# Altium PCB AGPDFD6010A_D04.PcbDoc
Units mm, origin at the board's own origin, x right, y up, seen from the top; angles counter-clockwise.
Board outline 100.4 x 100.27 mm, 2 copper layers (Top Layer, Bottom Layer), stack 1.57 mm thick; 22 components, 16 nets, 92 pads, 437 vias.
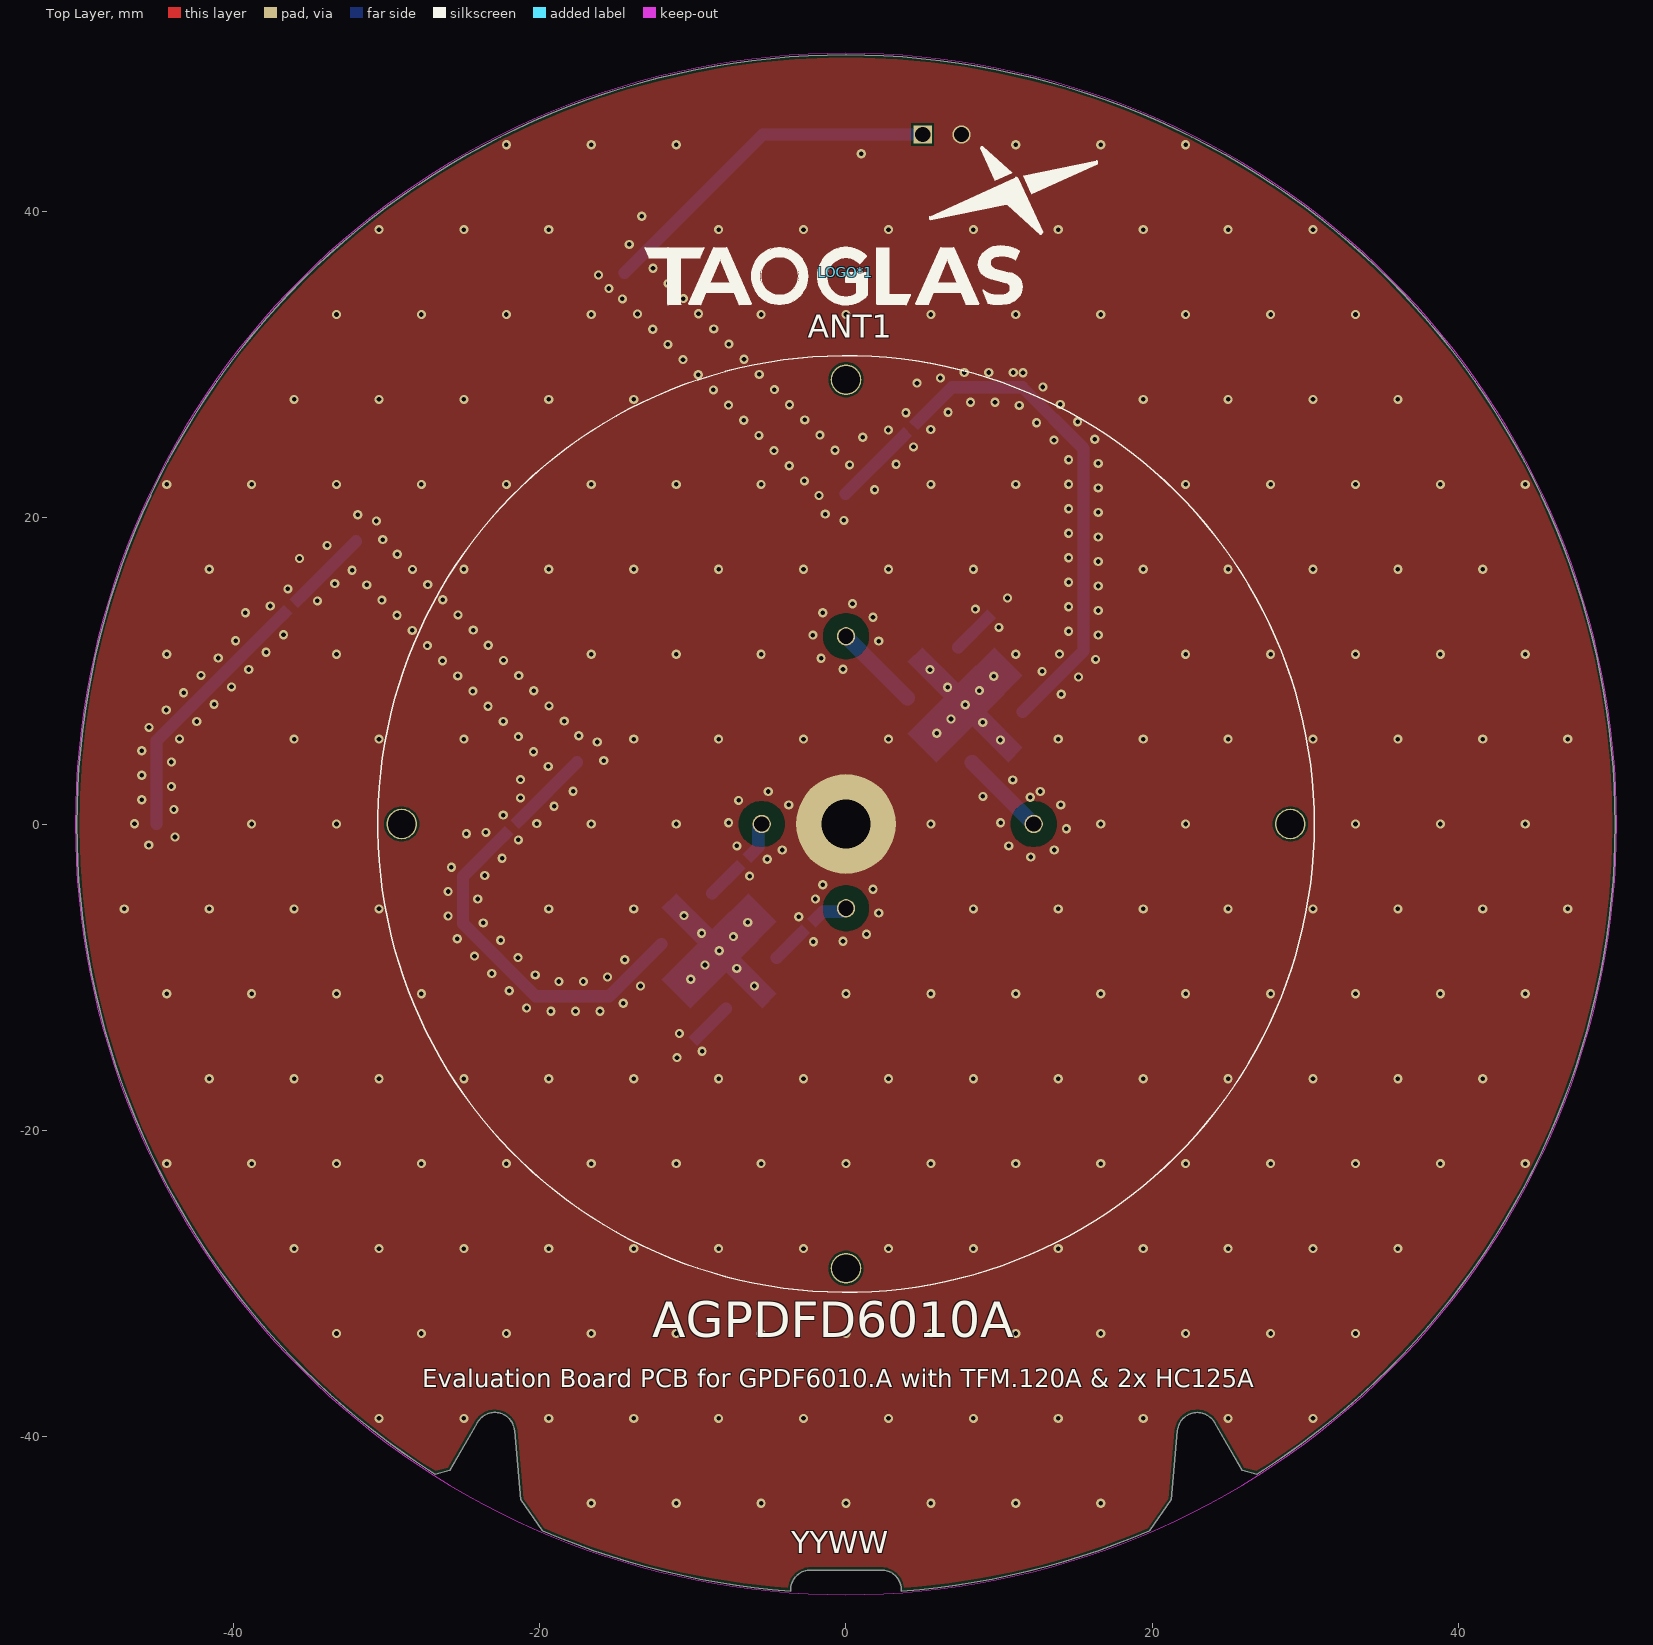
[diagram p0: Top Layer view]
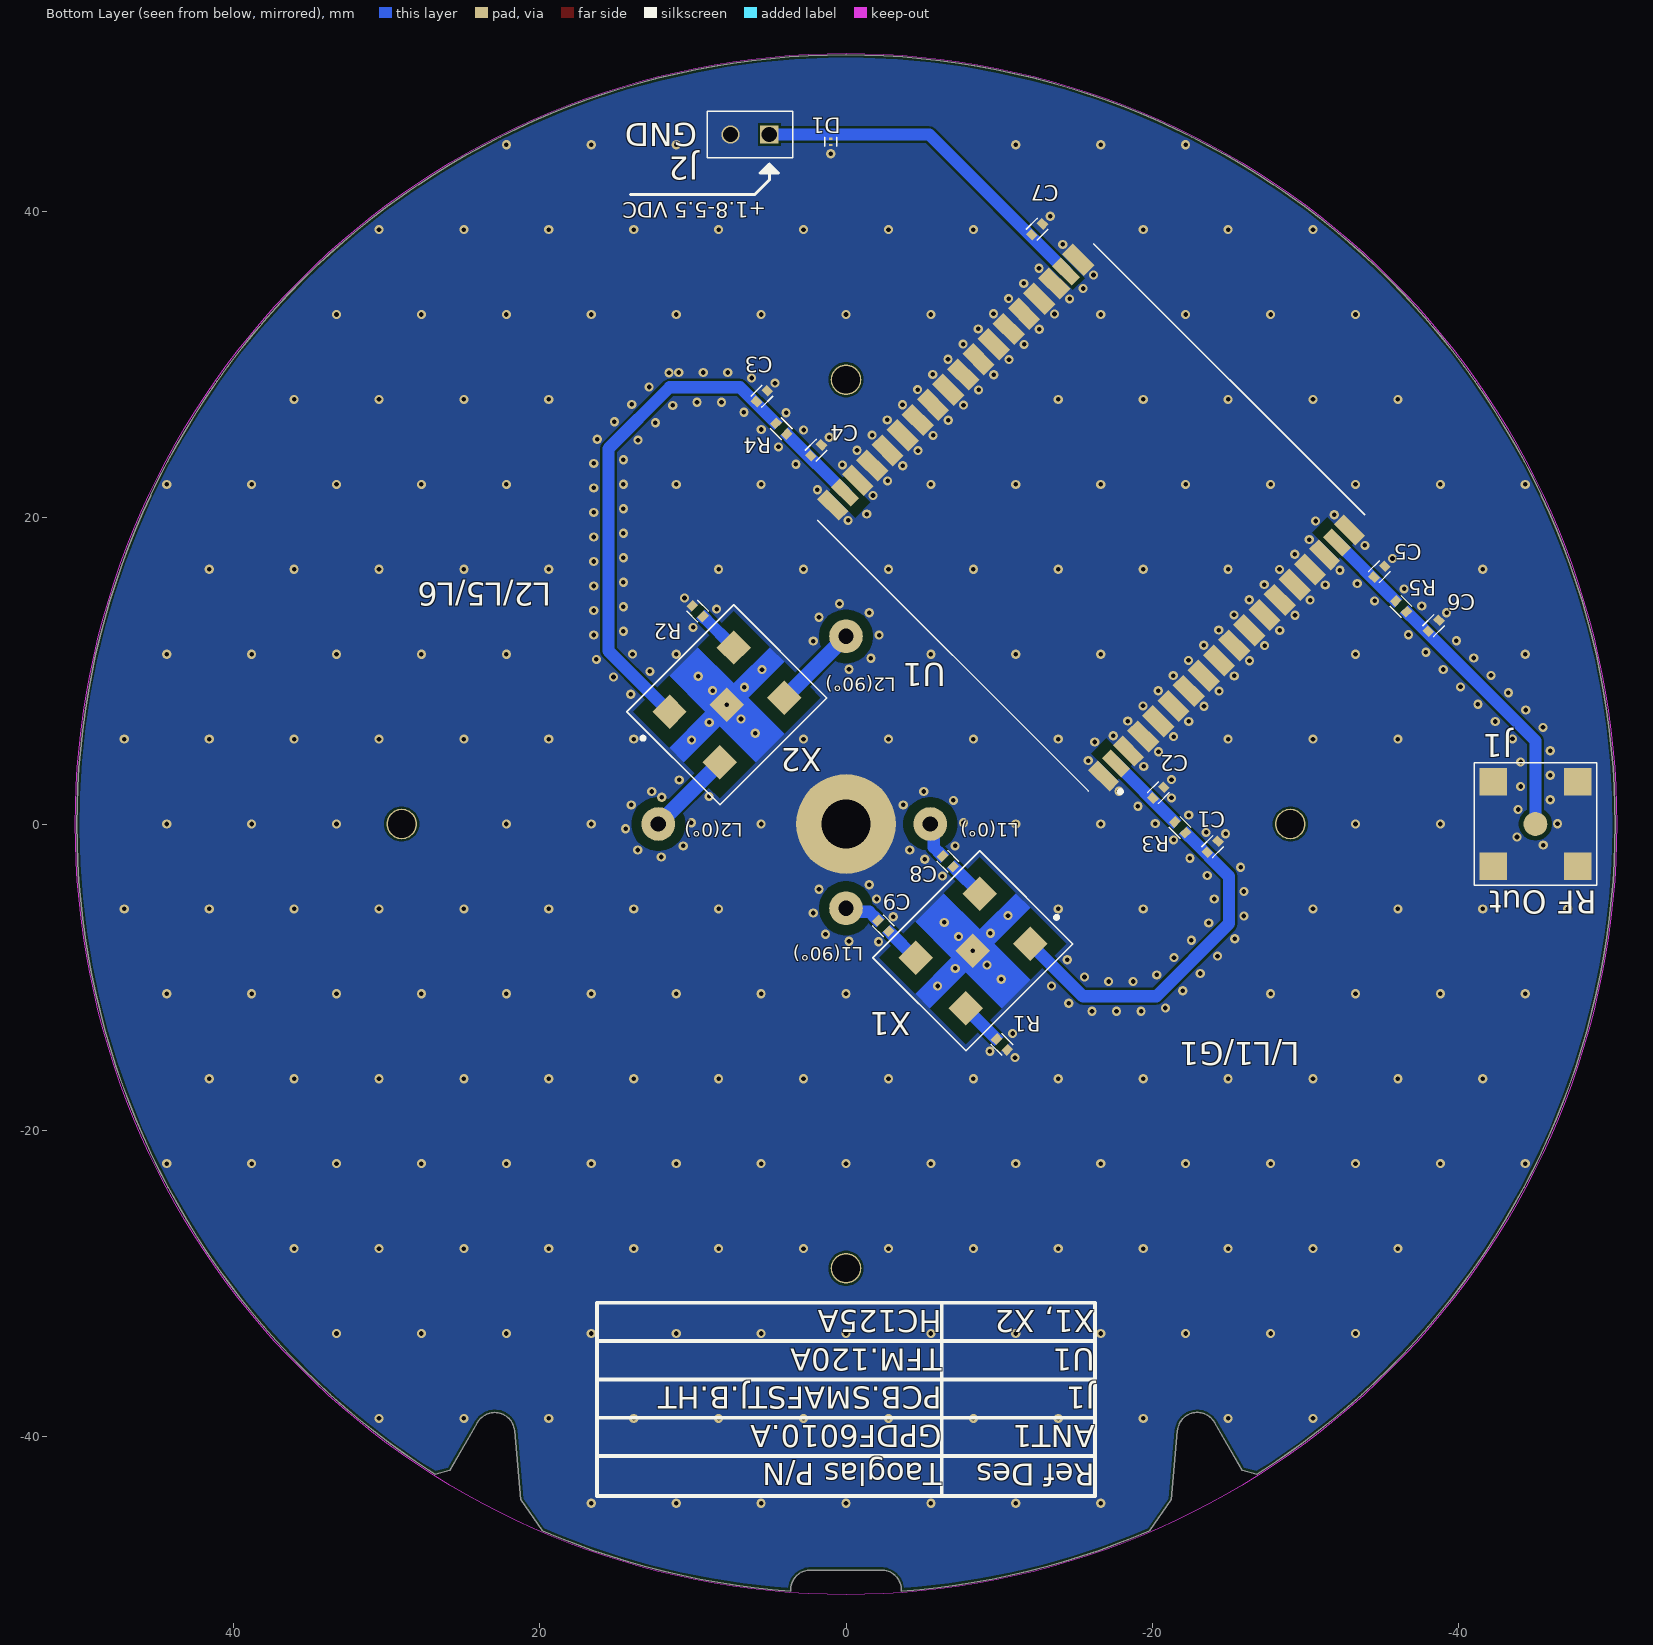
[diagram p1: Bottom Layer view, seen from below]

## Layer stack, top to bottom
Top Solder Mask: solder mask 0.01, Solder Resist, Dk 3.5
Top Layer: signal copper 0.035
Dielectric: core 1.5, FR-4, Dk 4.2
Bottom Layer: signal copper 0.035
Bottom Solder Mask: solder mask 0.01, Solder Resist, Dk 3.5

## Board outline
-19.822,-46.121 ccw(c0,0) -3.611,-50.07 -3.611,-49.992 cw(c-2.311,-49.992) -2.311,-48.692 2.311,-48.692 cw(c2.311,-49.992) 3.611,-49.992 3.611,-50.07 ccw(c0,0) 19.822,-46.121 21.236,-44.101 21.631,-39.593 cw(c22.926,-39.707) 24.052,-39.057 24.051,-39.057 25.857,-42.185 26.812,-42.44 ccw(c0,0) -26.812,-42.44 -25.857,-42.185 -24.051,-39.057 cw(c-22.926,-39.706) -21.632,-39.594 -21.63,-39.593 -21.236,-44.101

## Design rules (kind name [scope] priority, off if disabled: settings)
BoardOutlineClearance [All] p1: gap=0.196 ignorepadtopadclearanceinfootprint=FALSE
Clearance Clearance_Polygon [All] p1: gap=0.14 ignorepadtopadclearanceinfootprint=FALSE except(0.05: Arc-Arc Arc-Track Track-Track; 0.1: Arc-SMDPad Arc-THPad Track-SMDPad Track-THPad SMDPad-SMDPad SMDPad-THPad THPad-THPad; 0.2: Arc-Via Arc-Text Arc-Hole Track-Via Track-Text Track-Hole SMDPad-Via SMDPad-Text SMDPad-Hole THPad-Via THPad-Text THPad-Hole Via-Via Via-Text Via-Hole Fill-Text Fill-Hole Poly-Text Poly-Hole Region-Text Region-Hole Text-Text Text-Hole)
HoleSize [All] p1: absolutevalues=TRUE maxlimit=6 minlimit=0.15 maxpercent=80.000 minpercent=20.000
MinimumAnnularRing [All] p1: minimumring=0.1
MinimumSolderMaskSliver [All vs InPadClass('All Pads')] p1: minsoldermaskwidth=0.05
PolygonConnect [All] p1: connectstyle=Direct reliefconductorwidth=0.254 reliefentries=4 polygonreliefangle="90 Angle" airgapwidth=0.254
RoutingVias [All] p1: holewidth=0.3 width=0.8 viastyle="Through Hole" minholewidth=0.15 minwidth=0.65 maxholewidth=6 maxwidth=6.5
SilkToSilkClearance [All] p1: silktosilkclearance=0.1
SilkToSolderMaskClearance [IsPad or IsVia vs OnLayer('Top Overlay')] p1: minsilkscreentomaskgap=0.05 clearancetoexposedcopper=FALSE
SilkToSolderMaskClearance SilkToSolderMaskClearance_1 [IsPad or IsVia vs OnLayer('Bottom Overlay')] p2: minsilkscreentomaskgap=0.05 clearancetoexposedcopper=FALSE
SolderMaskExpansion [Not IsVia] p1: expansion=0.1 istentingtop=FALSE
Width [All] p1: maxlimit=5 minlimit=0.1 preferedwidth=1 minimp=50.000000 maximp=50.000000 favimp=50.000000
26 further rules are at their usual default settings.

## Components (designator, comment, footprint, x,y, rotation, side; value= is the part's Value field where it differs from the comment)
ANT1 "TAOGLAS_GPDF6010.A" TAOGLAS_GPDF6010.A 0,0 r0 top
C1 "DNF" "0402 - DNF" -23.923,-1.488 r135 bottom
C2 "DNF" "0402 - DNF" -20.388,2.048 r135 bottom
C3 "DNF" "0402 - DNF" 5.488,27.924 r135 bottom
C4 "DNF" "0402 - DNF" 1.952,24.388 r135 bottom
C5 "DNF" "0402 - DNF" -34.812,16.472 r315 bottom
C6 "DNF" "0402 - DNF" -38.348,12.936 r135 bottom
C7 "100pF" "Capacitor - 0402 - GRM" -12.472,38.812 r315 bottom
C8 "4.7pF" "Capacitor - 0402 - GRM" -6.653,-2.442 r45 bottom
C9 "4.7pF" "Capacitor - 0402 - GRM" -2.442,-6.653 r45 bottom
D1 "ESD245B1W0201E6327XTSA1" "Diode - 0201 (0603 Metric) - DSN0603-2" 1,44.525 r270 bottom
J1 "TAOGLAS_PCB.SMAFSTJ.B.HT" TAOGLAS_PCB.SMAFSTJ.B.HT -45,0 r270 bottom
J2 "PREC002SAAN-RC" SULLINS_PREC002SAAN-RC 6.27,45 r0 bottom
LOGO*1 "TAOGLAS_LOGO" "TAOGLAS_LOGO - No R - 10.3mm" 0,36 r0 top
R1 "Resistor_Thick Film_1005(0402)_49.9Ohms+-1%_0.063W" "Resistor - 0402 - RC_L" -10.179,-14.391 r225 bottom value=49.9
R2 "Resistor_Thick Film_1005(0402)_49.9Ohms+-1%_0.063W" "Resistor - 0402 - RC_L" 9.686,13.898 r45 bottom value=49.9
R3 "Resistor_Thick Film_1005(0402)_0Ohm" "Resistor - 0402 - RC_L" -21.802,-0.22 r225 bottom value=0
R4 "Resistor_Thick Film_1005(0402)_0Ohm" "Resistor - 0402 - RC_L" 4.22,25.802 r45 bottom value=0
R5 "Resistor_Thick Film_1005(0402)_0Ohm" "Resistor - 0402 - RC_L" -36.226,14.204 r225 bottom value=0
U1 "TAOGLAS_TFM.120A" TAOGLAS_TFM.120A -16,20 r45 bottom
X1 "TAOGLAS_HC125A" TAOGLAS_HC125A -8.275,-8.275 r315 bottom
X2 "TAOGLAS_HC125A" TAOGLAS_HC125A 7.782,7.782 r135 bottom

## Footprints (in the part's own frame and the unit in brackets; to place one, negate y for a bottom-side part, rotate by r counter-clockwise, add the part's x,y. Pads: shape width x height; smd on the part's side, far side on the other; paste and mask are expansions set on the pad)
"0402 - DNF" [mm]
  rect 0.5x0.6 smd paste-2539.97 mask+0.1: 1(-0.5,0) 2(0.5,0)
  silkscreen extent -0.5,-0.5 0.5,0.5
"Capacitor - 0402 - GRM" [mm]
  rect 0.5x0.6 smd mask+0.1: 1(-0.5,0) 2(0.5,0)
  silkscreen extent -0.5,-0.5 0.5,0.5, body extent -0.5,-0.25 0.5,0.25, height 0.55
"Diode - 0201 (0603 Metric) - DSN0603-2" [mm]
  rect 0.14x0.24 smd paste-2539.97 mask+0.05: 1(-0.2,0) 2(0.2,0)
  silkscreen extent -0.3,-0.4 0.3,0.4, body extent -0.3,-0.15 0.3,0.15, height 0.32
"Resistor - 0402 - RC_L" [mm]
  rect 0.5x0.6 smd mask+0.1: 1(-0.5,0) 2(0.5,0)
  silkscreen extent -0.5,-0.5 0.5,0.5, body extent -0.5,-0.25 0.5,0.25, height 0.4
SULLINS_PREC002SAAN-RC [mm] "2 Positions Header, 0.100\" (2.54mm)"
  rect 1.2x1.2 hole 1 mask+0.1: 1(-1.27,0)
  round 1.2 hole 1 mask+0.1: 2(1.27,0)
  silkscreen extent -2.79,-1.52 2.79,1.52, body extent -2.54,-1.27 2.54,1.27, height 8.38
TAOGLAS_GPDF6010.A [mm] "Passive All-band High Precision GNSS Stacked Dual Pin Dual Feed Patch Antenna"
  round 1.2 / inner round 2.2 / far side round 2.2 hole 1 paste-0.1 mask+0.1: 1(-5.5,0) 2(0,-5.5) 4(12.25,0) 5(0,12.25)
  round 6.5 hole 3.2 mask+0.1: 3(0,0)
  round 2 hole 1.8 unplated: ""(-29,0) ""(0,-29) ""(0,29) ""(29,0)
  Bottom Layer pour cut-out: -5.5,1.75 -4.83,1.617 -4.263,1.237 -3.883,0.67 -3.75,0 -3.75,0 -3.883,-0.67 -4.263,-1.238 -4.83,-1.617 -5.5,-1.75 -5.5,-1.75 -6.17,-1.617 -6.738,-1.238 -7.117,-0.67 -7.25,0 -7.25,0 -7.117,0.67 -6.738,1.237 -6.17,1.617 -5.5,1.75
  Bottom Layer pour cut-out: 0,-3.75 0.67,-3.883 1.237,-4.263 1.617,-4.83 1.75,-5.5 1.75,-5.5 1.617,-6.17 1.237,-6.738 0.67,-7.117 0,-7.25 0,-7.25 -0.67,-7.117 -1.238,-6.738 -1.617,-6.17 -1.75,-5.5 -1.75,-5.5 -1.617,-4.83 -1.238,-4.263 -0.67,-3.883 0,-3.75
  Bottom Layer pour cut-out: 12.25,1.75 12.92,1.617 13.487,1.237 13.867,0.67 14,0 14,0 13.867,-0.67 13.487,-1.238 12.92,-1.617 12.25,-1.75 12.25,-1.75 11.58,-1.617 11.012,-1.238 10.633,-0.67 10.5,0 10.5,0 10.633,0.67 11.012,1.237 11.58,1.617 12.25,1.75
  Bottom Layer pour cut-out: 0,14 0.67,13.867 1.237,13.487 1.617,12.92 1.75,12.25 1.75,12.25 1.617,11.58 1.237,11.012 0.67,10.633 0,10.5 0,10.5 -0.67,10.633 -1.238,11.012 -1.617,11.58 -1.75,12.25 -1.75,12.25 -1.617,12.92 -1.238,13.487 -0.67,13.867 0,14
  Multi-Layer pour cut-out: -5.5,1.5 -4.926,1.386 -4.439,1.061 -4.114,0.574 -4,0 -4,0 -4.114,-0.574 -4.439,-1.061 -4.926,-1.386 -5.5,-1.5 -5.5,-1.5 -6.074,-1.386 -6.561,-1.061 -6.886,-0.574 -7,0 -7,0 -6.886,0.574 -6.561,1.061 -6.074,1.386 -5.5,1.5
  Multi-Layer pour cut-out: 0,-4 0.574,-4.114 1.061,-4.439 1.386,-4.926 1.5,-5.5 1.5,-5.5 1.386,-6.074 1.061,-6.561 0.574,-6.886 0,-7 0,-7 -0.574,-6.886 -1.061,-6.561 -1.386,-6.074 -1.5,-5.5 -1.5,-5.5 -1.386,-4.926 -1.061,-4.439 -0.574,-4.114 0,-4
  Multi-Layer pour cut-out: 12.25,1.5 12.824,1.386 13.311,1.061 13.636,0.574 13.75,0 13.75,0 13.636,-0.574 13.311,-1.061 12.824,-1.386 12.25,-1.5 12.25,-1.5 11.676,-1.386 11.189,-1.061 10.864,-0.574 10.75,0 10.75,0 10.864,0.574 11.189,1.061 11.676,1.386 12.25,1.5
  Multi-Layer pour cut-out: 0,13.75 0.574,13.636 1.061,13.311 1.386,12.824 1.5,12.25 1.5,12.25 1.386,11.676 1.061,11.189 0.574,10.864 0,10.75 0,10.75 -0.574,10.864 -1.061,11.189 -1.386,11.676 -1.5,12.25 -1.5,12.25 -1.386,12.824 -1.061,13.311 -0.574,13.636 0,13.75
  silkscreen extent -30.56,-30.56 30.56,30.56, body extent -30.31,-30.31 30.31,30.31, height 11.97
TAOGLAS_HC125A [mm] "Low Profile, High Performance Multiband GNSS Hybrid Coupler"
  rect 1.6x1.6 smd paste-0.1 mask+0.1: 1(-2.96,2.325) 2(2.96,2.325) 3(2.96,-2.325) 4(-2.96,-2.325)
  rect 1.6x1.6 smd: 5(0,0)
  Top Layer region: -4.62,0.665 -4.62,-0.665 -1.3,-0.665 -1.3,-3.985 1.3,-3.985 1.3,-0.665 4.62,-0.665 4.62,0.665 1.3,0.665 1.3,3.985 -1.3,3.985 -1.3,0.665
  silkscreen extent -5.51,-4.3 4.94,4.3, body extent -3.17,-2.54 3.18,2.54, height 1.5
"TAOGLAS_LOGO - No R - 10.3mm" [mm] "Total Height from bottom of the text to the top of the star is 10.3mm"
  silkscreen extent -13.15,-2.12 16.43,8.2
TAOGLAS_PCB.SMAFSTJ.B.HT [mm] "SMA (F) Surface Mount PCB Jack"
  round 1.55 smd paste-0.1 mask+0.1: 1(0,0)
  rect 1.8x1.8 smd paste-0.1 mask+0.1: 2(-2.75,2.75) 3(2.75,2.75) 4(-2.75,-2.75) 5(2.75,-2.75)
  silkscreen extent -4,-4 4,4, body extent -3.5,-3.5 3.5,3.5, height 10.23
TAOGLAS_TFM.120A [mm] "Surface mount GNSS front-end module covering L1+B1+G1/L2/L5+L-band"
  rect 2x0.9 smd paste-2539.97 mask+0: 1(-12.5,11.35) 3(-12.5,9.05) 16(-12.5,-9.05) 18(-12.5,-11.35) 34(12.5,9.05) 36(12.5,11.35)
  rect 1.8x0.8 smd paste-2539.97 mask+0.1: 2(-12.5,10.2) 17(-12.5,-10.2) 20(12.5,-10.2) 35(12.5,10.2)
  rect 2x1 smd paste-2539.97 mask+0: 4(-12.5,7.7) 5(-12.5,6.3) 6(-12.5,4.9) 7(-12.5,3.5) 8(-12.5,2.1) 9(-12.5,0.7) 10(-12.5,-0.7) 11(-12.5,-2.1) 12(-12.5,-3.5) 13(-12.5,-4.9) 14(-12.5,-6.3) 15(-12.5,-7.7) 19(12.5,-11.3) 21(12.5,-9.1) 22(12.5,-7.7) 23(12.5,-6.3) 24(12.5,-4.9) 25(12.5,-3.5) 26(12.5,-2.1) 27(12.5,-0.7) 28(12.5,0.7) 29(12.5,2.1) 30(12.5,3.5) 31(12.5,4.9) 32(12.5,6.3) 33(12.5,7.7)
  silkscreen extent -14.1,-12.75 12.5,12.75, body extent -12.5,-12.5 12.5,12.5, height 4.51

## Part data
ANT1: library part CMP-519-000000-4, "Passive All-band High Precision GNSS Stacked Dual Pin Dual Feed Patch Antenna", Temp_High=+85C, Temp_Low=-40C
C1 C2 C3 C4 C5 C6: library part CMP-00006-25, "Do Not Fit"
C7: library part CMP-001-00343-45, "100 pF ±5% 50V Ceramic Capacitor C0G, NP0 0402 (1005 Metric)", Max. Operating Temperature=125°C, Min. Operating Temperature=-55°C, Package / Case="0402 (1005 Metric)", Temperature Coefficient="C0G, NP0", Tolerance=±5%, Voltage - Rated=50V
C8 C9: library part CMP-001-00399-44, "4.7 pF ±0.25pF 50V Ceramic Capacitor C0G, NP0 0402 (1005 Metric)", Max. Operating Temperature=125°C, Min. Operating Temperature=-55°C, Package / Case="0402 (1005 Metric)", Temperature Coefficient="C0G, NP0", Tolerance=±0.25pF, Voltage - Rated=50V
D1: library part CMP-004-00167-10, "7.5V Clamp 5.5A (8/20µs) Ipp Tvs Diode Surface Mount WLL-2-3", Capacitance @ Frequency="5.8pF @ 1GHz", Current - Peak Pulse (10/1000µs)="5.5A (8/20µs)", Max. Operating Temperature=125°C, Max. Voltage - Clamping @ Ipp=7.5V, Min. Operating Temperature=-55°C, Package / Case="0201 (0603 Metric)", Power - Peak Pulse=44W, Power Line Protection=No, Supplier Device Package=WLL-2-3, Voltage - Reverse Standoff (Typ)=5.5V
J1: library part CMP-028-000009-10, "SMA (F) Surface Mount PCB Jack", Temp_High=+85C, Temp_Low=-40C
J2: library part CMP-002-00180-7, "Connector Header Through Hole 2 position 0.100\" (2.54mm)", Temp_High=105°C, Temp_Low=-40°C
LOGO*1: library part CMP-048-000000-3, "Silkscreen Logo - Standard"
R1 R2: library part CMP-009-00330-4, "49.9 Ohms ±1% 0.1W, 1/10W Chip Resistor 0402 (1005 Metric) Automotive AEC-Q200 Thick Film", Max. Operating Temperature=155°C, Min. Operating Temperature=-55°C, Package / Case="0402 (1005 Metric)", Power (Watts)=63mW, Temperature Coefficient=±100ppm/°C, Tolerance=±1%
R3 R4 R5: library part CMP-009-00375-4, "0 Ohms Jumper Chip Resistor 0402 (1005 Metric) Moisture Resistant Thick Film", Max. Operating Temperature=155°C, Min. Operating Temperature=-55°C, Package / Case="0402 (1005 Metric)"
U1: library part CMP-272-000001-5, "Surface mount GNSS front-end module covering L1+B1+G1/L2/L5+L-band", Temp_High=+85C, Temp_Low=-40C
X1 X2: library part CMP-002-000151-19, "Low Profile, High Performance Multiband GNSS Hybrid Coupler", Center Frequency=1.39GHz

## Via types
v1: diameter 0.6, hole 0.3, Top Layer to Bottom Layer, tented both sides, 437 vias

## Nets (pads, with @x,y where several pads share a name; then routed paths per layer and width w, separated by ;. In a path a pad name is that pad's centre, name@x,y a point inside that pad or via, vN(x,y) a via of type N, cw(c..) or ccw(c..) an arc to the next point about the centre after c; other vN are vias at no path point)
GND: ANT1.3 C1.2 C2.2 C3.2 C4.2 C5.1 C6.2 C7.1 D1.2 J1.2 J1.3 J1.4 J1.5 J2.2 R1.2 R2.2 U1.1 U1.3 U1.4 U1.5 U1.6 U1.7 U1.8 U1.9 U1.10 U1.11 U1.12 U1.13 U1.14 U1.15 U1.16 U1.18 U1.19 U1.21 U1.22 U1.23 U1.24 U1.25 U1.26 U1.27 U1.28 U1.29 U1.30 U1.31 U1.32 U1.33 U1.34 U1.36 X1.5 X2.5
  other v1: -16.626,-44.336 -11.084,-44.336 -5.542,-44.336 0,-44.336 5.542,-44.336 11.084,-44.336 16.626,-44.336 -30.481,-38.794 -24.939,-38.794 -19.397,-38.794 -13.855,-38.794 -8.313,-38.794 -2.771,-38.794 2.771,-38.794 8.313,-38.794 13.855,-38.794 19.397,-38.794 24.939,-38.794 30.481,-38.794 -33.252,-33.252 -27.71,-33.252 -22.168,-33.252 -16.626,-33.252 -11.084,-33.252 -5.542,-33.252 0,-33.252 5.542,-33.252 11.084,-33.252 16.626,-33.252 22.168,-33.252 27.71,-33.252 33.252,-33.252 -36.023,-27.71 -30.481,-27.71 -24.939,-27.71 -19.397,-27.71 -13.855,-27.71 -8.313,-27.71 -2.771,-27.71 2.771,-27.71 8.313,-27.71 13.855,-27.71 19.397,-27.71 24.939,-27.71 30.481,-27.71 36.023,-27.71 -44.336,-22.168 -38.794,-22.168 -33.252,-22.168 -27.71,-22.168 -22.168,-22.168 -16.626,-22.168 -11.084,-22.168 -5.542,-22.168 0,-22.168 5.542,-22.168 11.084,-22.168 16.626,-22.168 22.168,-22.168 27.71,-22.168 33.252,-22.168 38.794,-22.168 44.336,-22.168 -41.565,-16.626 -36.023,-16.626 -30.481,-16.626 -24.939,-16.626 -19.397,-16.626 -13.855,-16.626 -8.313,-16.626 -2.771,-16.626 2.771,-16.626 8.313,-16.626 13.855,-16.626 19.397,-16.626 24.939,-16.626 30.481,-16.626 36.023,-16.626 41.565,-16.626 -11.033,-15.245 -9.392,-14.83 -10.874,-13.673 -19.258,-12.219 -17.658,-12.219 -16.058,-12.219 -20.844,-12.008 -14.543,-11.702 -44.336,-11.084 -38.794,-11.084 -33.252,-11.084 -27.71,-11.084 0,-11.084 5.542,-11.084 11.084,-11.084 16.626,-11.084 22.168,-11.084 27.71,-11.084 33.252,-11.084 38.794,-11.084 44.336,-11.084 -21.984,-10.886 -13.412,-10.571 -5.977,-10.573 -18.738,-10.281 -17.138,-10.281 -10.131,-10.131 -15.566,-9.985 -20.279,-9.851 -23.115,-9.754 -7.126,-9.424 -9.203,-9.203 -14.434,-8.854 -21.411,-8.719 -24.247,-8.623 -8.275,-8.275 -2.13,-7.688 -0.196,-7.652 -22.542,-7.588 -25.378,-7.492 -7.347,-7.347 1.337,-7.195 -9.424,-7.126 -23.673,-6.457 -6.419,-6.419 -3.08,-6.055 -25.969,-6.005 -10.573,-5.977 2.137,-5.81 -47.107,-5.542 -41.565,-5.542 -36.023,-5.542 -30.481,-5.542 -19.397,-5.542 -13.855,-5.542 8.313,-5.542 13.855,-5.542 19.397,-5.542 24.939,-5.542 30.481,-5.542 36.023,-5.542 41.565,-5.542 47.107,-5.542 -24.031,-4.897 -1.996,-4.893 -25.969,-4.405 1.765,-4.253 -1.513,-3.959 -6.292,-3.402 -23.576,-3.363 -25.755,-2.819 -5.137,-2.295 -22.444,-2.232 12.054,-2.152 -4.163,-1.695 13.587,-1.695 -7.124,-1.43 10.626,-1.43 -45.503,-1.376 -21.378,-1.039 -43.792,-0.85 -24.777,-0.634 -23.5,-0.548 14.387,-0.31 -38.794,0 -33.252,0 -16.626,0 -11.084,0 5.542,0 16.626,0 22.168,0 33.252,0 38.794,0 44.336,0 -46.438,0.022 -20.185,0.027 -7.659,0.078 10.091,0.078 -22.375,0.58 -43.867,0.949 -19.054,1.158 -3.735,1.247 14.015,1.247 -7.013,1.541 -45.969,1.579 -21.246,1.706 12.02,1.744 8.933,1.803 -5.075,2.122 12.675,2.122 -17.813,2.136 -44.031,2.447 10.888,2.876 -21.241,2.901 -45.969,3.179 -19.439,3.762 -44.031,4.047 -15.813,4.136 -20.394,4.717 -45.969,4.779 -16.23,5.352 10.08,5.484 -43.503,5.558 -36.023,5.542 -30.481,5.542 -24.939,5.542 -13.855,5.542 -8.313,5.542 -2.771,5.542 2.771,5.542 13.855,5.542 19.397,5.542 24.939,5.542 30.481,5.542 36.023,5.542 41.565,5.542 47.107,5.542 -21.384,5.707 -17.439,5.762 5.926,5.926 -45.494,6.307 8.931,6.633 -42.372,6.689 -22.374,6.696 -18.394,6.717 6.854,6.854 -44.362,7.438 -23.364,7.686 -19.384,7.706 7.782,7.782 -41.24,7.82 14.046,8.465 -43.231,8.57 -24.354,8.676 -20.374,8.696 8.71,8.71 6.633,8.931 -40.109,8.952 15.177,9.597 9.638,9.638 -25.344,9.666 -42.1,9.701 -21.364,9.686 12.801,9.96 -38.978,10.083 5.484,10.08 -0.196,10.098 -26.334,10.656 -22.354,10.676 16.292,10.745 -1.624,10.82 -40.968,10.832 -44.336,11.084 -33.252,11.084 -16.626,11.084 -11.084,11.084 -5.542,11.084 11.084,11.084 13.932,11.091 22.168,11.084 27.71,11.084 33.252,11.084 38.794,11.084 44.336,11.084 -37.846,11.214 -27.324,11.646 -23.344,11.666 -39.837,11.964 2.137,11.94 -2.159,12.328 16.469,12.335 -36.715,12.346 14.531,12.574 -28.314,12.636 -24.334,12.656 9.977,12.835 1.765,13.497 -29.304,13.626 -25.324,13.646 -39.201,13.79 -1.513,13.791 16.469,13.935 8.448,14.029 14.531,14.174 -37.574,14.226 0.425,14.372 -34.499,14.562 -30.294,14.616 -26.314,14.636 10.54,14.751 -36.427,15.342 16.469,15.535 -31.283,15.606 -27.304,15.626 -33.368,15.693 14.531,15.774 -32.238,16.561 -41.565,16.626 -28.294,16.616 -24.939,16.626 -19.397,16.626 -13.855,16.626 -8.313,16.626 -2.771,16.626 2.771,16.626 8.313,16.626 19.397,16.626 24.939,16.626 30.481,16.626 36.023,16.626 41.565,16.626 16.469,17.135 -35.666,17.326 14.531,17.374 -29.283,17.606 -33.864,18.187 -30.238,18.561 16.469,18.735 14.531,18.974 -30.651,19.774 -0.135,19.813 -31.864,20.187 -1.349,20.226 16.469,20.335 14.531,20.574 -1.762,21.44 1.865,21.813 16.469,21.935 -44.336,22.168 -38.794,22.168 -33.252,22.168 -27.71,22.168 -22.168,22.168 -16.626,22.168 -11.084,22.168 -5.542,22.168 5.542,22.168 11.084,22.168 14.531,22.174 22.168,22.168 27.71,22.168 33.252,22.168 38.794,22.168 44.336,22.168 -2.716,22.394 -3.706,23.384 0.238,23.44 3.271,23.483 16.469,23.535 14.531,23.774 -4.696,24.374 -0.716,24.394 4.403,24.615 13.574,25.056 16.237,25.118 1.099,25.242 -5.686,25.364 -1.706,25.384 2.767,25.718 5.534,25.746 12.443,26.188 15.113,26.257 -6.676,26.354 -2.696,26.374 3.91,26.838 6.665,26.878 11.311,27.319 -7.666,27.344 -3.686,27.364 13.982,27.388 8.126,27.531 9.726,27.531 -36.023,27.71 -30.481,27.71 -24.939,27.71 -19.397,27.71 -13.855,27.71 19.397,27.71 24.939,27.71 30.481,27.71 36.023,27.71 -8.656,28.334 -4.676,28.354 12.85,28.52 4.634,28.777 6.161,29.112 -9.646,29.324 -5.666,29.344 11.554,29.458 7.72,29.469 9.32,29.469 10.92,29.469 -10.636,30.314 -6.656,30.334 -11.626,31.304 -7.646,31.324 -12.616,32.294 -8.636,32.314 -33.252,33.252 -27.71,33.252 -22.168,33.252 -16.626,33.252 -5.542,33.252 0,33.252 5.542,33.252 11.084,33.252 16.626,33.252 22.168,33.252 27.71,33.252 33.252,33.252 -13.606,33.284 -9.626,33.304 -14.596,34.274 -10.616,34.294 -15.474,34.951 -11.606,35.284 -16.151,35.829 -12.596,36.274 -14.151,37.829 -30.481,38.794 -24.939,38.794 -19.397,38.794 -8.313,38.794 -2.771,38.794 2.771,38.794 8.313,38.794 13.855,38.794 19.397,38.794 24.939,38.794 30.481,38.794 -13.325,39.666 1,43.74 -22.168,44.336 -16.626,44.336 -11.084,44.336 11.084,44.336 16.626,44.336 22.168,44.336
NetANT1_1: ANT1.1 C8.2 | length 2.3
  Bottom Layer w0.8: C8.2@-6.194,-1.983 -5.73,-1.518 -5.73,-0.229 ANT1.1
NetANT1_2: ANT1.2 C9.2 | length 2.3
  Bottom Layer w0.8: C9.2@-1.983,-6.194 -1.518,-5.729 -0.23,-5.729 ANT1.2
NetANT1_4: ANT1.4 X2.4 | length 5.7
  Bottom Layer w1: X2.4@8.231,4.019 ANT1.4
NetANT1_5: ANT1.5 X2.3 | length 5.7
  Bottom Layer w1: ANT1.5 X2.3@4.019,8.231
NetC1_1: C1.1 R3.2 X1.1 | length 23.3
  Bottom Layer w0.8: R3.2@-22.27,-0.687 -25,-3.418 -25,-6.5 -20.25,-11.25 -15.461,-11.25 X1.1@-12.037,-7.826
NetC2_1: C2.1 R3.1 U1.2 | length 5.4
  Bottom Layer w0.8: R3.1@-21.343,0.239 U1.2@-17.557,4.025
NetC3_1: C3.1 R4.2 X2.1 | length 32.2
  Bottom Layer w0.8: R4.2@4.681,26.264 6.918,28.5 11.5,28.5 15.5,24.5 15.5,11.289 X2.1@11.544,7.333
NetC4_1: C4.1 R4.1 U1.35 | length 5.3
  Bottom Layer w0.8: U1.35@-0.025,21.557 R4.1@3.743,25.325
NetC5_2: C5.2 R5.1 U1.17 | length 5.2
  Bottom Layer w0.8: -35.64,14.79 U1.17@-31.981,18.449
NetC6_1: C6.1 J1.1 R5.2 | length 17
  Bottom Layer w0.8: J1.1 -45,5.431 -36.794,13.637
NetC7_2: C7.2 D1.1 J2.1 U1.20 | length 23.2
  Bottom Layer w0.8: U1.20@-14.449,35.981 -5.431,45 -2.5,45 J2.1
NetC8_1: C8.1 X1.4 | length 2.3
  Bottom Layer w0.8: X1.4@-8.724,-4.512 C8.1@-7.113,-2.902
NetC9_1: C9.1 X1.3 | length 2.3
  Bottom Layer w0.8: X1.3@-4.512,-8.724 C9.1@-2.902,-7.113
NetR1_1: R1.1 X1.2 | length 2.7
  Bottom Layer w0.8: R1.1@-9.716,-13.928 X1.2@-7.826,-12.037
NetR2_1: R2.1 X2.2 | length 2.7
  Bottom Layer w0.8: X2.2@7.333,11.544 R2.1@9.219,13.431
pads on no net: ANT1.

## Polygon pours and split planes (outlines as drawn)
GND on Top Layer "GND_L01_P000" (solid, remove dead copper, pour order 0): -19.822,-46.121 ccw(c0,0) -3.611,-50.07 -3.611,-49.992 cw(c-2.311,-49.992) -2.311,-48.692 2.311,-48.692 cw(c2.311,-49.992) 3.611,-49.992 3.611,-50.07 ccw(c0,0) 19.822,-46.121 21.236,-44.101 21.631,-39.593 cw(c22.926,-39.707) 24.052,-39.057 24.051,-39.057 25.857,-42.185 26.812,-42.44 ccw(c0,0) -26.812,-42.44 -25.857,-42.185 -24.051,-39.057 cw(c-22.926,-39.706) -21.632,-39.594 -21.63,-39.593 -21.236,-44.101
GND on Bottom Layer "GND_L02_P001" (solid, remove dead copper, pour order 1): -19.822,-46.121 ccw(c0,0) -3.611,-50.07 -3.611,-49.992 cw(c-2.311,-49.992) -2.311,-48.692 2.311,-48.692 cw(c2.311,-49.992) 3.611,-49.992 3.611,-50.07 ccw(c0,0) 19.822,-46.121 21.236,-44.101 21.631,-39.593 cw(c22.926,-39.707) 24.052,-39.057 24.051,-39.057 25.857,-42.185 26.812,-42.44 ccw(c0,0) -26.812,-42.44 -25.857,-42.185 -24.051,-39.057 cw(c-22.926,-39.706) -21.632,-39.594 -21.63,-39.593 -21.236,-44.101

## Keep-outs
Keep-Out Layer:
  circle w0.001: c0,0 r50.3

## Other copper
Top Layer:
  text ".Layer_Name" at -94.75,22.334 h2
Bottom Layer:
  region net NetC5_2: -36.332,14.664 -35.767,14.098 -35.307,14.558 -35.873,15.124
  region net NetC6_1: -37.146,13.851 -36.58,13.285 -36.12,13.745 -36.686,14.31
  region net NetC2_1: -21.908,0.24 -21.343,-0.326 -20.883,0.134 -21.449,0.699
  region net NetC4_1: 3.301,25.449 3.867,24.883 4.326,25.343 3.761,25.908
  region net NetC3_1: 4.114,26.262 4.68,25.696 5.139,26.156 4.574,26.722
  region net NetR2_1: 8.767,13.544 9.333,12.979 9.792,13.438 9.227,14.004
  region net NetC1_1: -22.721,-0.574 -22.156,-1.139 -21.696,-0.679 -22.262,-0.114
  region net NetC8_1: -6.547,-2.902 -7.113,-2.336 -7.679,-2.902 -7.113,-3.467
  region net NetR1_1: -10.286,-13.931 -9.72,-14.497 -9.26,-14.037 -9.826,-13.472
  region net NetANT1_1: -5.628,-1.983 -6.194,-1.417 -6.76,-1.983 -6.194,-2.548
  region net NetANT1_2: -1.417,-6.194 -1.983,-5.628 -2.548,-6.194 -1.983,-6.76
  region net NetC9_1: -2.336,-7.113 -2.902,-6.547 -3.467,-7.113 -2.902,-7.679
  pour cut-out: -43.925,0 cw(c-45,0) -45,-1.075 cw(c-45,0) -46.075,0 cw(c-45,0) -45,1.075 cw(c-45,0) -43.925,0
  pour cut-out: -30.426,19.015 -31.416,20.005 -33.113,18.308 -32.123,17.318
  pour cut-out: -13.989,35.663 -14.768,36.442 -15.574,35.635 -14.795,34.857
  pour cut-out: -35.66,13.991 -36.44,14.771 -36.793,14.417 -36.013,13.638
  pour cut-out: -16.001,4.591 -16.991,5.581 -18.688,3.884 -17.698,2.894
  pour cut-out: 4.787,25.589 4.007,26.369 3.653,26.016 4.433,25.236
  pour cut-out: 1.106,21.699 0.116,22.689 -1.581,20.992 -0.591,20.002
  pour cut-out: 7.333,9.193 9.684,11.544 7.332,13.896 4.981,11.544
  pour cut-out: 4.02,5.879 6.371,8.231 4.019,10.583 1.668,8.231
  pour cut-out: 8.231,1.668 10.583,4.019 8.231,6.371 5.879,4.02
  pour cut-out: 9.12,14.111 9.9,13.331 10.253,13.685 9.473,14.465
  pour cut-out: 11.544,4.981 13.895,7.333 11.544,9.685 9.192,7.333
  pour cut-out: -21.235,-0.433 -22.015,0.347 -22.369,-0.007 -21.589,-0.787
  pour cut-out: -6.087,-2.655 -6.867,-1.875 -7.22,-2.229 -6.44,-3.009
  pour cut-out: -8.724,-6.864 -6.372,-4.513 -8.724,-2.161 -11.076,-4.512
  pour cut-out: -12.037,-10.177 -9.685,-7.826 -12.037,-5.474 -14.389,-7.825
  pour cut-out: -7.826,-14.389 -5.474,-12.037 -7.826,-9.686 -10.177,-12.037
  pour cut-out: -9.613,-14.604 -10.393,-13.824 -10.746,-14.178 -9.966,-14.958
  pour cut-out: -1.875,-6.867 -2.655,-6.087 -3.009,-6.44 -2.229,-7.22
  pour cut-out: -4.512,-11.076 -2.161,-8.724 -4.513,-6.372 -6.864,-8.724
  text ".Layer_Name" at -94.75,17.334 h2

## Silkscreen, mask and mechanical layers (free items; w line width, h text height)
Top Overlay:
  region: 195.273,23.862 195.273,24.315
  text ".Layer_Name" at -94.75,12.334 h2
  text "AGPDFD6010A" at -12.643,-34.281 h4
  text "Evaluation Board PCB for GPDF6010.A with TFM.120A & 2x HC125A" at -27.656,-37.138 h2
  text "YYWW" at -3.588,-48.101 h2.5
Bottom Overlay:
  rectangle: 4.599,42.419 5.41,42.747
  rectangle: 4.771,42.639 5.224,42.924
  lines w0.2: 5.006,42.992 5.006,42.03 5.955,41.081 14.057,41.081 ; 4.409,42.481 5.006,43.078 5.603,42.481 4.409,42.481
  lines w0.254: -16.25,-41.25 16.25,-41.25 ; -16.25,-38.75 16.25,-38.75 ; -16.25,-36.25 16.25,-36.25 ; -16.25,-33.75 16.25,-33.75 ; -6.25,-43.85 -6.25,-31.25 ; -16.25,-43.85 16.25,-43.85 16.25,-31.25 -16.25,-31.25 -16.25,-43.85
  text "GND" at 9.701,45.75 h1.5 r180
  text "+1.8-5.5 VDC" at 5.208,40.578 h1 r180
  text "L2/L5/L6" at 19.252,15.75 h1.5 r180
  text "L2(90°)" at -3.234,9.847 h1.5 r180
  text ".Layer_Name" at -94.75,7.334 h2
  text "L1(0°)" at -11.261,0.347 h1.5 r180
  text "L2(0°)" at 6.739,0.347 h1.5 r180
  text "RF Out" at -48.999,-4.35 h1.5 r180
  text "L1(90°)" at -1.134,-7.753 h1.5 r180
  text "L/L1/G1" at -29.623,-14.25 h1.5 r180
  text "X1, X2" at -16.25,-31.25 h2.5 r180
  text "HC125A" at -6.25,-31.25 h2.5 r180
  text "U1" at -16.25,-33.75 h2.5 r180
  text "TFM.120A" at -6.25,-33.75 h2.5 r180
  text "J1" at -16.25,-36.25 h2.5 r180
  text "PCB.SMAFSTJ.B.HT" at -6.25,-36.25 h2.5 r180
  text "ANT1" at -16.25,-38.75 h2.5 r180
  text "GPDF6010.A" at -6.25,-38.75 h2.5 r180
  text "Taoglas P/N" at -6.25,-41.229 h2.5 r180
  text "Ref Des" at -16.25,-41.25 h2.5 r180
Top Paste:
  text ".Layer_Name" at -94.75,-7.666 h2
Bottom Paste:
  text ".Layer_Name" at -94.75,-13 h2
Top Solder Mask:
  text ".Layer_Name" at -94.75,2.334 h2
Bottom Solder Mask:
  text ".Layer_Name" at -94.75,-3 h2
Board Outline:
  lines w0.2: -21.632,-39.594 ccw(c-22.926,-39.706) -24.051,-39.057 -25.857,-42.185 -26.812,-42.44 cw(c0,0) 26.812,-42.44 25.857,-42.185 24.051,-39.057 ; -21.63,-39.593 -21.236,-44.101 -19.822,-46.121 ccw(c0,0) -3.611,-50.07 -3.611,-49.992 cw(c-2.311,-49.992) -2.311,-48.692 2.311,-48.692 cw(c2.311,-49.992) 3.611,-49.992 3.611,-50.07 ccw(c0,0) 19.822,-46.121 21.236,-44.101 21.631,-39.593 cw(c22.926,-39.707) 24.052,-39.057
  text ".Layer_Name" at -94.75,27 h2
Top Assembly:
  text ".Layer_Name" at -94.75,-17.666 h2
Bottom Assembly:
  text ".Layer_Name" at -94.75,-22.666 h2
IDW:
  drawing of 191 lines, arcs and shapes, not listed
  text "Layer" at -59.651,-61.65 h1.52
  text "Name" at -49.24,-61.65 h1.52
  text "Material" at -19.784,-61.65 h1.52
  text "Thickness" at 2.054,-61.65 h1.52
  text "Constant" at 18.56,-61.65 h1.52
  text "Board Layer Stack" at 33.034,-61.65 h1.52
  text "Top Overlay" at -49.24,-64.698 h1.52
  text "Top Solder Mask" at -49.24,-67.746 h1.52
  text "Solder Resist" at -19.784,-67.746 h1.52
  text "0.010mm" at 2.054,-67.746 h1.52
  text "3.5" at 18.56,-67.746 h1.52
  text "1" at -59.651,-70.794 h1.52
  text "Top Layer" at -49.24,-70.794 h1.52
  text "0.035mm" at 2.054,-70.794 h1.52
  text "Dielectric" at -49.24,-73.842 h1.52
  text "FR-4" at -19.784,-73.842 h1.52
  text "1.500mm" at 2.054,-73.842 h1.52
  text "4.2" at 18.56,-73.842 h1.52
  text "2" at -59.651,-76.89 h1.52
  text "Bottom Layer" at -49.24,-76.89 h1.52
  text "0.035mm" at 2.054,-76.89 h1.52
  text "Bottom Solder Mask" at -49.24,-79.938 h1.52
  text "Solder Resist" at -19.784,-79.938 h1.52
  text "0.010mm" at 2.054,-79.938 h1.52
  text "3.5" at 18.56,-79.938 h1.52
  text "Bottom Overlay" at -49.24,-82.986 h1.52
